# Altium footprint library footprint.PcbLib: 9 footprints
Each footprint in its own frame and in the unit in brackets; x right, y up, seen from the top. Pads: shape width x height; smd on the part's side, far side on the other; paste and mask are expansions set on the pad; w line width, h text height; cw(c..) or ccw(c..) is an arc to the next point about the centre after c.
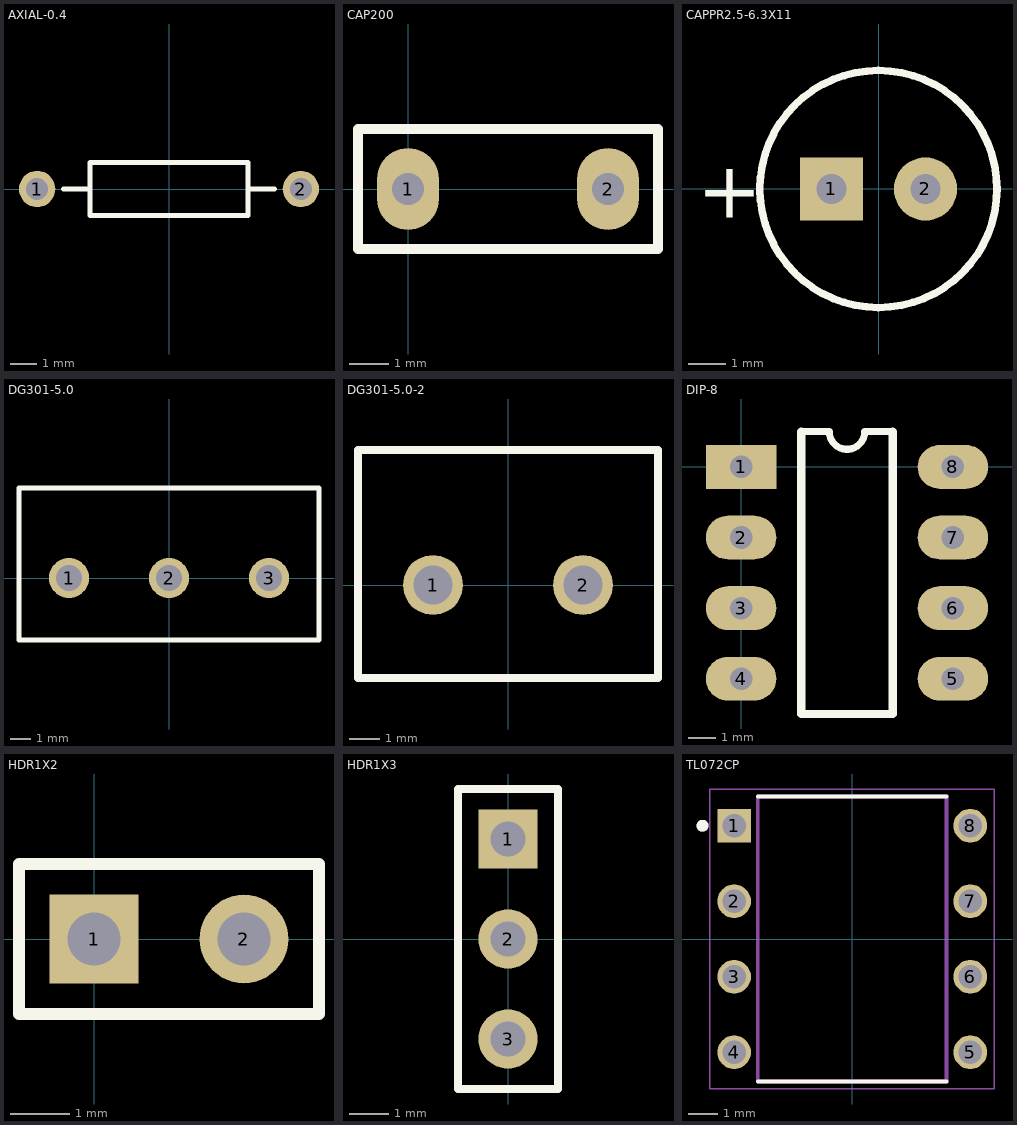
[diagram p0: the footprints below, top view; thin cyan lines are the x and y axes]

## AXIAL-0.4 [mm] "Axial Device, Thru-Hole; 2 Leads; 0.4 in Pin Spacing"
height 2.032
pads (2):
  round 1.4 hole 0.85: 1(-5.08,0) 2(5.08,0)
Top Overlay:
  lines w0.2: -4.064,0 -3.048,0 ; 3.048,0 4.064,0 ; -3.048,-1.016 3.048,-1.016 3.048,1.016 -3.048,1.016 -3.048,-1.016
3D body "Resistor0.25W.STEP": height 3.71, standoff -2.54, extent -5.55,-1.27 5.55,1.23

## CAP200 [mil]
height 270.08
pads (2):
  oval 62x82 hole 32: 1(0,0) 2(200,0)
Top Overlay:
  lines w10: -50,-60 250,-60 250,0 250,60 -50,60 -50,-60
3D body "Kondenzator v2.step": height 245.8, standoff -76.38, extent -10.68,-39.37 209.96,39.37

## CAPPR2.5-6.3X11 [mil]
pads (2):
  rect 66x66 hole 31.5: 1(-49.38,-0.05)
  round 66 hole 31.5: 2(49.05,-0.05)
Top Overlay:
  circle w7.87: c-0.16,-0.05 r124.02
  text "+" at -190,-30 h59.05
3D body "User Library-Cap electro 6_3x11x2_5mm.step": height 118.67, standoff -453.76, extent -126.18,-125.06 123.85,124.97

## DG301-5.0 [mm]
pads (3):
  round 2 hole 1.3: 1(-5,0) 2(0,0) 3(5,0)
Top Overlay:
  lines w0.254: -7.5,-3.1 7.5,-3.1 7.5,4.5 -7.5,4.5 -7.5,-3.1
3D body "691102710003.stp": height 5, standoff -8.5, extent -8.1,-3.3 8.1,4.2

## DG301-5.0-2 [mm]
pads (2):
  round 2 hole 1.3: 1(-2.5,0) 2(2.5,0)
Top Overlay:
  lines w0.254: -5,-3.1 5,-3.1 5,4.5 -5,4.5 -5,-3.1

## DIP-8 [mil]
pads (8):
  rect 100x62 hole 32: 1(0,0)
  oval 100x62 hole 32: 2(0,-100) 3(0,-200) 4(0,-300) 5(300,-300) 6(300,-200) 7(300,-100) 8(300,0)
Top Overlay:
  lines w10: 85,50 125,50 ccw(c150,50) 175,50 215,50
  lines w11.81: 85,50 85,-350 215,-350 215,50
3D body "LM358AP.STEP": height 200, standoff -150, extent -4.99,-338.74 305,38.76

## HDR1X2 [mm] "Connector; Header; 2 Position"
height 4.7
pads (2):
  rect 1.5x1.5 hole 0.9: 1(0,0)
  round 1.5 hole 0.9: 2(2.54,0)
Top Overlay:
  lines w0.2: -1.27,-1.27 -1.27,1.27 3.81,1.27 3.81,-1.27 -1.27,-1.27
3D body "Download_STP_61300211121 (rev1).stp": height 8.79, standoff -2.75, extent -1.27,-1.27 3.81,1.27

## HDR1X3 [mm]
pads (3):
  rect 1.5x1.5 hole 0.9: 1(0,2.54)
  round 1.5 hole 0.9: 2(0,0) 3(0,-2.54)
Top Overlay:
  lines w0.2: -1.27,-3.81 1.27,-3.81 1.27,3.81 -1.27,3.81 -1.27,-3.81
3D body "Pin Header 1x3 TH Pitch 2.54mm.stp": height 9.5, standoff -3.2, extent -1.27,-3.81 1.27,3.81

## TL072CP [mm]
pads (8):
  rect 1.13x1.13 hole 0.78: 1(-3.97,3.81)
  round 1.13 hole 0.78: 2(-3.97,1.27) 3(-3.97,-1.27) 4(-3.97,-3.81) 5(3.97,-3.81) 6(3.97,-1.27) 7(3.97,1.27) 8(3.97,3.81)
Top Overlay:
  circle w0.2: c-5.035,3.81 r0.1
  lines w0.127: -3.175,-4.795 3.175,-4.795 ; -3.175,4.795 3.175,4.795
Mechanical 13:
  circle w0.2: c-5.035,3.81 r0.1
  lines w0.127: -3.175,-4.795 -3.175,4.795 3.175,4.795 3.175,-4.795 -3.175,-4.795
Mechanical 15:
  lines w0.05: -4.785,-5.045 -4.785,5.045 4.785,5.045 4.785,-5.045 -4.785,-5.045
